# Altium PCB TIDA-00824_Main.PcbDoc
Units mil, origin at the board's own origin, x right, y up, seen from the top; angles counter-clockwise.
Board outline 1575 x 1140 mil, 4 copper layers (Top Layer, GND, PWR, Bottom Layer), stack 60.8 mil thick; 37 components, 28 nets, 124 pads, 44 vias.
Unrouted connection lines stored in the file: 2.
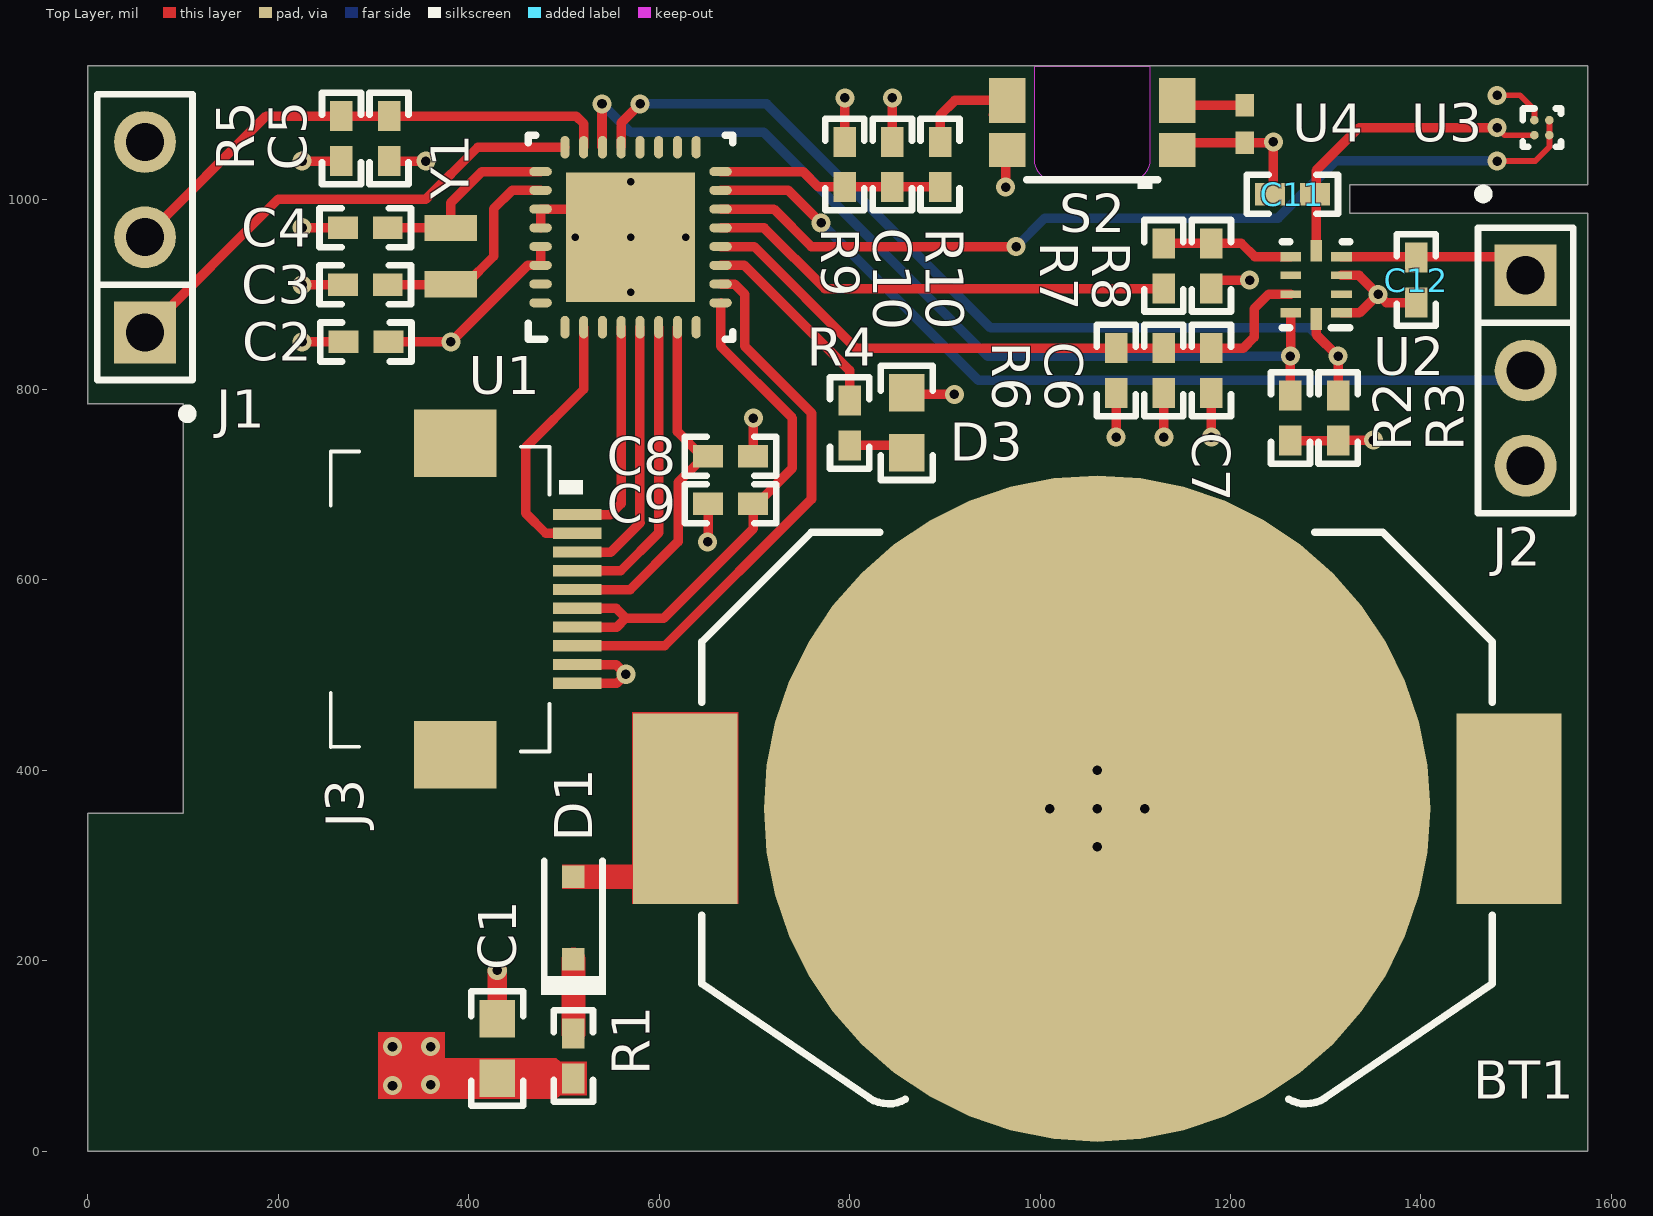
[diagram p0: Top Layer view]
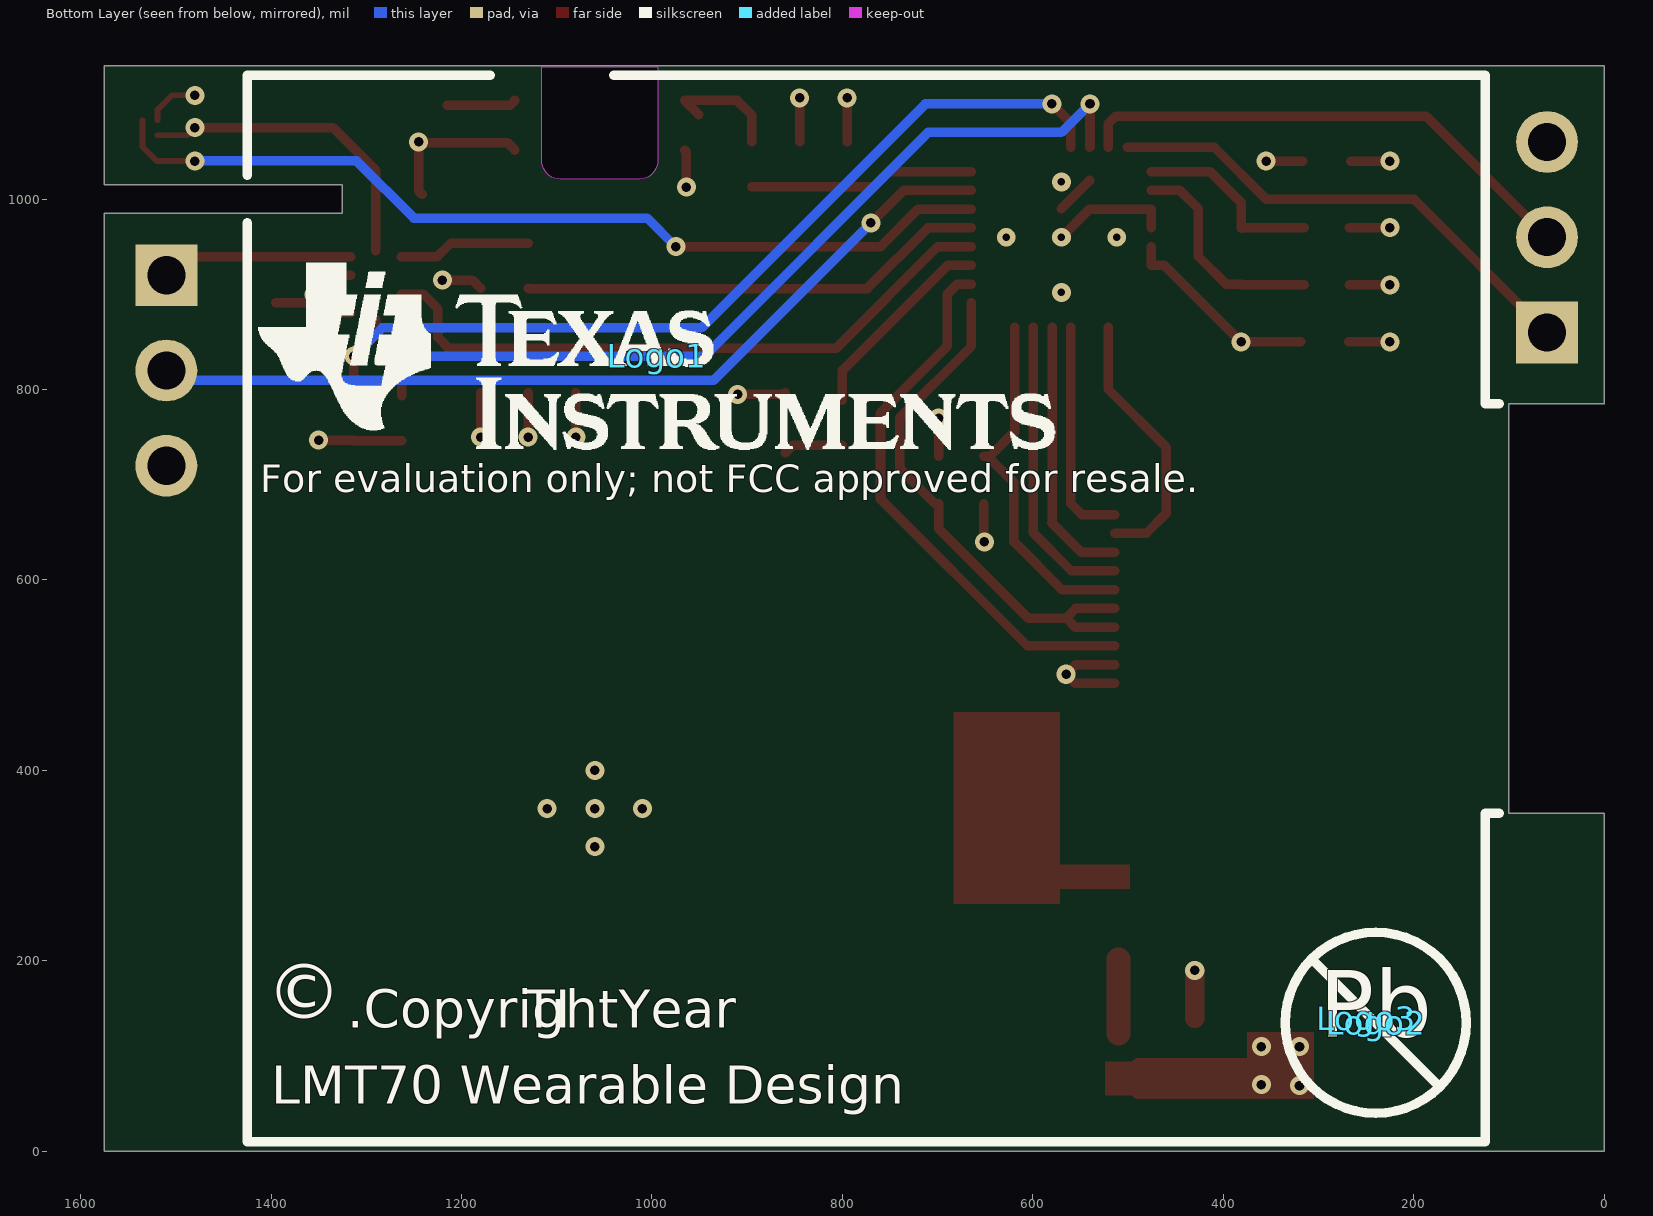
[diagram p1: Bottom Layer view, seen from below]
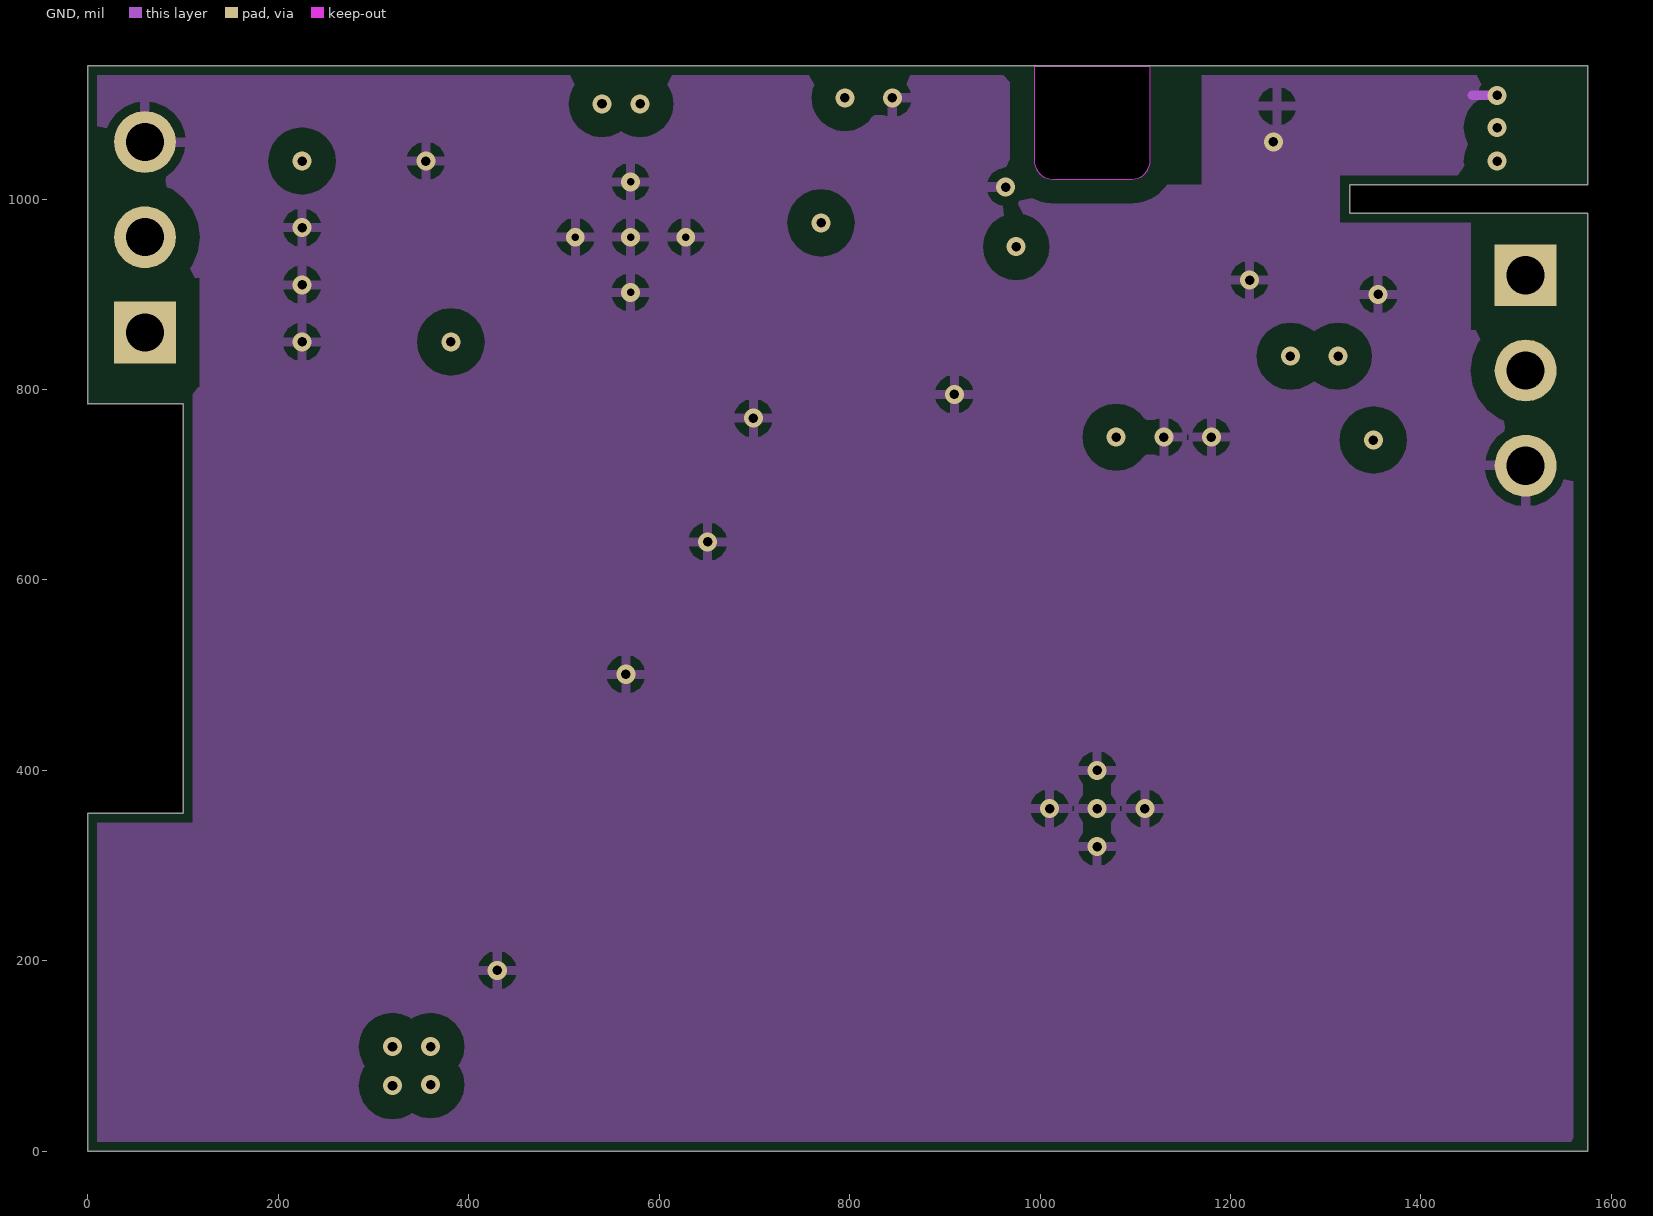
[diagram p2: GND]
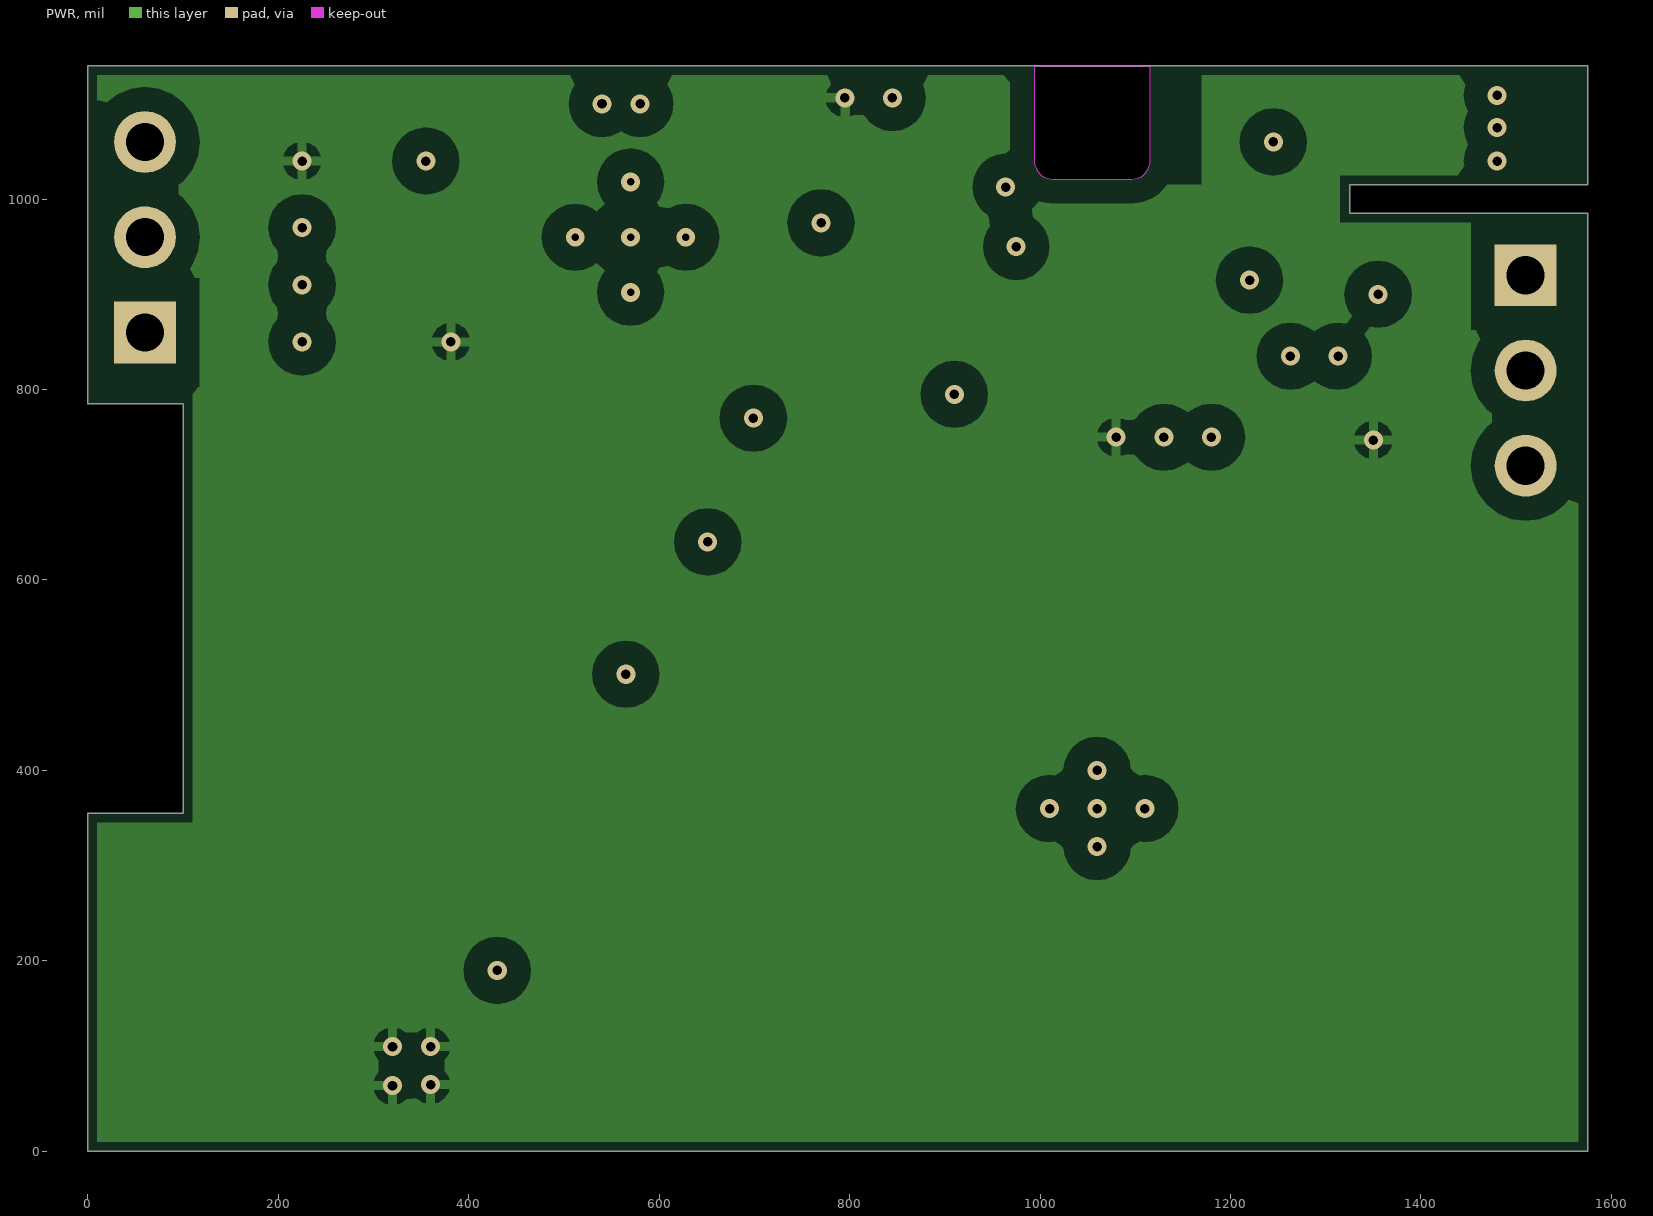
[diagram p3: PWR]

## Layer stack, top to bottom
Top Solder: solder mask 0.4, Solder Resist, Dk 3.5
Top Layer: signal copper 1.4
Dielectric1: core 12.6, FR-4, Dk 4.8
GND: signal copper 1.4
Dielectric2: prepreg 30, FR-4, Dk 4.8
PWR: signal copper 1.4
Dielectric3: core 12.6, FR-4, Dk 4.8
Bottom Layer: signal copper 1.4
Bottom Solder: solder mask 0.4, Solder Resist, Dk 3.5

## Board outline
0,0 0,355 100,355 100,785 0,785 0,1140 1575,1140 1575,1015 1325,1015 1325,985 1575,985 1575,0

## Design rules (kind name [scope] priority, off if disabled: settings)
AcuteAngle [All] p1: minimum=4.50000000000000E+0001 checktracksonly=FALSE
AssemblyTestPointUsage [All] p1: valid=2
Clearance Clearance_BoardEdge_MountingHoles [OnCopper and InComponentClass('Mounting Holes') vs IsKeepOut] p1: gap=40
Clearance Clearance_BoardEdge_Poly [OnCopper and InPoly vs IsKeepOut] p2: gap=25
Clearance Clearance_BoardEdge [OnCopper and Not InComponentClass('Logo') and not InComponentClass('FiducialMark') and not InRegion(1000,500,4000,800) and Not IsKeepout vs IsKeepOut] p3: gap=75
Clearance Clearance_Poly [InPolygon] p4: gap=25
Clearance [All] p5: gap=7.87
ComponentClearance ComponentClearance_Shunt [InComponentClass('Header') vs InComponentClass('Shunt')] p1: gap=0 collisioncheckmode=3 verticalgap=0 showdistances=FALSE
ComponentClearance ComponentClearance_MountingHoles_FiducialMarks [InComponentClass('Mounting Holes') vs InComponentClass('FiducialMark')] p2: gap=50 collisioncheckmode=3 verticalgap=10 showdistances=FALSE
ComponentClearance ComponentClearance_Logo [InComponentClass('Logo')] p3: gap=50 collisioncheckmode=3 verticalgap=10 showdistances=FALSE
ComponentClearance ComponentClearance_ScrewToNut [(HasFootprint('NY PMS 440 0025 PH')) vs (HasFootprint('Keystone_1902C'))] p4: gap=5 collisioncheckmode=3 verticalgap=10 showdistances=FALSE
ComponentClearance ComponentClearance_MountingHoles [InComponentClass('Mounting Holes')] p5: gap=250 collisioncheckmode=3 verticalgap=100000 showdistances=FALSE
ComponentClearance ComponentClearance_SmallPassives [HasFootprint('0201*') or HasFootprint('0402*') or HasFootprint('0508') or HasFootprint('0603*') or HasFootprint('0612') or HasFootprint('0805*') or HasFootprint('0815*') or HasFootprint('0830*') or HasFootprint('1206*') or HasFootprint('1210*') or HasFootprint('1808*') or HasFootprint('1812*') or HasFootprint('1825*') or HasFootprint('2010*') or HasFootprint('2220*') or HasFootprint('2225*') or HasFootprint('2512*') or HasFootprint('2728*') or HasFootprint('3518*') vs HasFootprint('0201*') or HasFootprint('0402*') or HasFootprint('0508') or HasFootprint('0603*') or HasFootprint('0612') or HasFootprint('0805*') or HasFootprint('0815*') or HasFootprint('0830*') or HasFootprint('1206*') or HasFootprint('1210*') or HasFootprint('1808*') or HasFootprint('1812*') or HasFootprint('1825*') or HasFootprint('2010*') or HasFootprint('2220*') or HasFootprint('2225*') or HasFootprint('2512*') or HasFootprint('2728*') or HasFootprint('3518*')] p6: gap=20 collisioncheckmode=3 verticalgap=10 showdistances=FALSE
ComponentClearance ComponentClearance_THtoSMT [IsThruComponent vs IsSMTComponent] p7: gap=50 collisioncheckmode=3 verticalgap=30 showdistances=FALSE
ComponentClearance ComponentClearance_THtoTH [IsThruComponent vs IsThruComponent] p8: gap=118.11 collisioncheckmode=3 verticalgap=30 showdistances=FALSE
ComponentClearance [All] p9: gap=40 collisioncheckmode=3 verticalgap=10 showdistances=FALSE
DiffPairsRouting [All] p1: maxlimit=100 minlimit=10 mostfreqgap=10 toplayer_minwidth=15 toplayer_maxwidth=15 toplayer_prefwidth=15 midlayer1_minwidth=15 midlayer1_maxwidth=15 midlayer1_prefwidth=15 midlayer2_minwidth=15 midlayer2_maxwidth=15 midlayer2_prefwidth=15 bottomlayer_minwidth=15 bottomlayer_maxwidth=15 bottomlayer_prefwidth=15 maxuncoupledlength=1000
FabricationTestPointUsage TestPointUsage [All] p1: valid=2 allowmultiple=FALSE
FabricationTestpoint Testpoint [All] p1: side=3 testpointundercomponent=TRUE minsize=40 maxsize=100 preferedsize=60 minholesize=0 maxholesize=40 preferedholesize=32 testpointgrid=1 allowsidetop=TRUE allowsidebottom=TRUE usegrid=TRUE gridtolerance=0.01
FanoutControl Fanout_LCC [IsLCC] p1: bgadir=Out bgaviamode=Centered fanoutstyle=Auto fanoutdirection=Alternating viagrid=1 // Fanout_LCC (Default Rule)
FanoutControl Fanout_BGA [IsBGA] p2: bgadir=Out bgaviamode=Centered fanoutstyle=Auto fanoutdirection=Alternating viagrid=1 // Fanout_BGA (Default Rule)
FanoutControl Fanout_Default [All] p4: bgadir=Out bgaviamode=Centered fanoutstyle=Auto fanoutdirection=Alternating viagrid=1 // Fanout_Default (Default Rule)
FanoutControl Fanout_Small [(CompPinCount < 5)] p5: bgadir=Out bgaviamode=Centered fanoutstyle=Auto fanoutdirection=OutThenIn viagrid=1 // Fanout_Small (Default Rule)
HoleSize [All] p1: absolutevalues=TRUE maxlimit=251 minlimit=7.87 maxpercent=80.000 minpercent=20.000
MinimumAnnularRing MinimumAnnularRing_ThermalPadVias [IsVia and InAnyComponent] p1: minimumring=5.91
MinimumAnnularRing [All] p2: minimumring=5
MinimumSolderMaskSliver MinimumSolderMaskSliver_Logo [InComponentClass('Logo') vs InComponentClass('Logo')] p1: minsoldermaskwidth=0.7
MinimumSolderMaskSliver [All] p2: minsoldermaskwidth=3.94
PlaneConnect [All] p1: planeconnectstyle=Relief reliefexpansion=10 reliefentries=4 reliefconductorwidth=10 reliefairgap=10
PolygonConnect [All] p1: connectstyle=Relief reliefconductorwidth=10 reliefentries=4 polygonreliefangle="90 Angle" airgapwidth=10
RoutingVias ThermalPadVias [IsVia and InAnyComponent] p1: holewidth=7.87 width=19.68 viastyle="Through Hole" minholewidth=7.87 minwidth=19.68 maxholewidth=12.99 maxwidth=23.62
RoutingVias [All] p2: holewidth=16 width=34 viastyle="Through Hole" minholewidth=7.87 minwidth=26 maxholewidth=40 maxwidth=65
SMDToCorner [All] p1 off: distance=30000
SilkToSilkClearance SilkToSilkClearance_Pb-FreeLogo [(HasFootprint('Pb-Free_Overlay_Medium') OR HasFootprint('Pb-Free_Overlay_Small')) vs (HasFootprint('Pb-Free_Overlay_Medium') OR HasFootprint('Pb-Free_Overlay_Small'))] p1: silktosilkclearance=0
SilkToSilkClearance [All] p2: silktosilkclearance=5
SilkToSolderMaskClearance SilkscreenOverComponentPads [IsPad] p1: minsilkscreentomaskgap=5 clearancetoexposedcopper=TRUE
SolderMaskExpansion [All] p1: expansion=1.97
UnpouredPolygon [All] p1: allowunpoured=FALSE
Width [All] p1: maxlimit=100 minlimit=6 preferedwidth=10 checkconnectedcopper=TRUE
15 further rules are at their usual default settings.

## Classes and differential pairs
component class Header: J1 J2
component class Logo: Logo1

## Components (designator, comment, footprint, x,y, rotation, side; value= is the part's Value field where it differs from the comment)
BT1 "BK-912" MPD_BK-912 1060,360 r0 top
C1 "C1608X5R1A106M" 0603 430,108 r90 top
C2 "GRM155R71C104JA88D" 0402 292,850 r180 top
C3 "GRM1555C1E120JA01D" 0402 291.38,910 r0 top
C4 "GRM1555C1E120JA01D" 0402 291.38,970 r0 top
C5 "C1005X7R1H222K" 0402 316.38,1063.62 r270 top
C6 "GRM155R71C104JA88D" 0402 1130,820 r270 top
C7 "GRM1535C1H101JDD5D" 0402 1180,820 r270 top
C8 "GRM155R71C104JA88D" 0402 675,730 r0 top
C9 "GRM155R6YA105KE11D" 0402 675,680 r180 top
C10 "GRM155R6YA105KE11D" 0402 845,1036.38 r90 top
C11 "GRM155R61E102KA01D" 0402 1265,1005 r180 top
C12 "GRM155R61E102KA01D" 0402 1395,915 r270 top
D1 "1SS315TPH3F" sod-323 510,245 r90 top
D3 "SML-LX0603SRW-TR" 0603 860,765 r90 top
J1 "TSW-103-07-G-S" TSW-103-07-G-S 60,960 r90 top
J2 "TSW-103-07-G-S" TSW-103-07-G-S 1510,820 r270 top
J3 "FH12-10S-0.5SH[55]" Hirose_FH12-10S-0_5SH[55] 450,580 r270 top
Logo1 "Texas Instruments" TI_Stacked_Overlay_Small 995,835 r180 bottom
Logo2 "Pb-Free Symbol" Pb-Free_Overlay_Medium 240,135 r180 bottom
Logo3 "FCC disclaimer" FCC_disclaimer 250,140 r180 bottom
R1 "CRCW040212R1FKED" 0402 510,100 r270 top
R2 "CRCW040210K0JNED" 0402 1263,770 r270 top
R3 "CRCW040210K0JNED" 0402 1313,770 r270 top
R4 "ERJ-2GEJ102X" 0402 800,765 r270 top
R5 "CRCW040233K0JNED" 0402 266.38,1063.62 r90 top
R6 "CRCW04020000Z0ED" 0402 1080,820 r270 top
R7 "CRCW0402100KFKED" 0402 1130,930 r270 top
R8 "CRCW0402100KFKED" 0402 1180,930 r90 top
R9 "CRCW0402100KFKED" 0402 795,1036.38 r270 top
R10 "CRCW0402100KFKED" 0402 895,1036.38 r270 top
S2 "EVP-ANDA1A" SW_EVPANDA 1054.88,1139.05 r180 top
U1 "MSP430G2553IRHB32R" RHB0032E 570,960 r90 top
U2 "ADS1115IRUGR" RUG0010A 1290,910 r180 top
U3 "LMT70YFQR" YFQ0004ACAC 1527.05,1075.08 r0 top
U4 "TPD1E10B06DPYR" DPY0002A 1214.88,1079.05 r270 top
Y1 "FC-12M 32.7680KA-A3" Epson_FC-12M 381.38,940 r270 top

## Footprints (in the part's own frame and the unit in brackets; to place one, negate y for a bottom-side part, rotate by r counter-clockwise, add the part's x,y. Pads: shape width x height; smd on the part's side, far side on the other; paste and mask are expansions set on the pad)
0402 [mm] "0402 from SM-752 data"
  rect 0.8x0.6 smd: 1(-0.6,0) 2(0.6,0)
  silkscreen extent -1.22,-0.52 1.22,0.52, body extent -0.55,-0.3 0.55,0.3, height 0.6
0603 [mm] "0603 from SM-752 data"
  rect 1x0.95 smd: 1(-0.8,0) 2(0.8,0)
  silkscreen extent -1.52,-0.69 1.52,0.69, body extent -0.87,-0.47 0.87,0.47, height 0.85
DPY0002A [mm] "R-PX2SON-N2"
  rect 0.6x0.5 smd: 1(-0.5,0) 2(0.5,0)
  body extent -0.55,-0.35 0.55,0.35, height 0.4
Epson_FC-12M [mm] "Epson"
  rect 0.7x1.4 smd: 1(-0.75,0) 2(0.75,0)
  body extent -1.05,-0.63 1.05,0.63, height 0.6
FCC_disclaimer [mil]
Hirose_FH12-10S-0_5SH[55] [mm] "Hirose, footprint recommended"
  rect 0.3x1.3 smd: 1(-2.254,1.626) 2(-1.754,1.626) 3(-1.254,1.626) 4(-0.754,1.626) 5(-0.253,1.626) 6(0.246,1.626) 7(0.746,1.626) 8(1.246,1.626) 9(1.746,1.626) 10(2.247,1.626)
  rect 1.8x2.2 smd: M1(-4.153,-1.622) M2(4.153,-1.626)
  silkscreen extent -4.06,-4.95 4.07,1.78, body extent -4.55,-4.88 4.56,0.84, height 2
MPD_BK-912 [mm] "Battery Holder for CR2032, SMT"
  rect 2.79x5.08 smd: 1(-10.985,0) 2(10.985,0)
  round 17.78 smd: 3(0,0)
  silkscreen extent -10.54,-7.88 10.54,7.37, body extent -11.43,-7.88 11.43,7.37, height 4.33
Pb-Free_Overlay_Medium [mil]
  silkscreen extent -95,-95 95,95
RHB0032E [mm] "QFN, 32-Leads, Body 5x5mm, Pitch 0.5mm, Thermal Pad 3.45x3.45mm, TI Recommended"
  oval 0.6x0.24 smd: 1(-2.4,1.75) 2(-2.4,1.25) 3(-2.4,0.75) 4(-2.4,0.25) 5(-2.4,-0.25) 6(-2.4,-0.75) 7(-2.4,-1.25) 8(-2.4,-1.75) 17(2.4,-1.75) 18(2.4,-1.25) 19(2.4,-0.75) 20(2.4,-0.25) 21(2.4,0.25) 22(2.4,0.75) 23(2.4,1.25) 24(2.4,1.75)
  oval 0.24x0.6 smd: 9(-1.75,-2.4) 10(-1.25,-2.4) 11(-0.75,-2.4) 12(-0.25,-2.4) 13(0.25,-2.4) 14(0.75,-2.4) 15(1.25,-2.4) 16(1.75,-2.4) 25(1.75,2.4) 26(1.25,2.4) 27(0.75,2.4) 28(0.25,2.4) 29(-0.25,2.4) 30(-0.75,2.4) 31(-1.25,2.4) 32(-1.75,2.4)
  rect 3.45x3.45 smd paste-1.725: 33(0,0)
  silkscreen extent -2.72,-2.73 2.72,2.73, body extent -2.57,-2.57 2.58,2.58, height 1.01
RUG0010A [mm] "QFN, 10-Leads, Body 2x1.5mm. Pitch 0.5mm, TI Recommended"
  rect 0.55x0.25 smd: 1(-0.675,0.75) 4(-0.675,-0.75) 6(0.675,-0.75) 9(0.675,0.75)
  rect 0.55x0.2 smd: 2(-0.675,0.25) 3(-0.675,-0.25) 7(0.675,-0.25) 8(0.675,0.25)
  rect 0.3x0.575 smd: 5(0,-0.913) 10(0,0.913)
  silkscreen extent -0.9,-1.15 0.9,1.15, body extent -0.77,-1.02 0.77,1.02, height 0.41
sod-323 [mm] "NXP recommended land pattern"
  rect 0.6x0.6 smd paste-0.05: 1(-1.1,0) 2(1.1,0)
  silkscreen extent -2.06,-0.86 1.53,0.86, body extent -1.3,-0.67 1.3,0.68, height 1.1
SW_EVPANDA [mm] "SMT, 4-Leads, Body 3.5x2.9mm, Pitch 1.325mm"
  rect 0.975x0.9 smd mask-5: 1(-2.262,2.225) 2(2.262,2.225)
  rect 0.975x1.2 smd mask-5: 3(-2.262,0.9) 4(2.262,0.9)
  Keep-Out Layer board cut-out: -1.55,0 1.55,0 1.55,2.5 1.512,2.691 1.404,2.854 1.241,2.962 1.05,3 1.05,3 -1.05,3 -1.241,2.962 -1.404,2.854 -1.512,2.691 -1.55,2.5 -1.55,2.5
  silkscreen extent -1.75,3.01 1.75,3.26, body extent -2.6,-0.49 2.6,3.22, height 0.85
TI_Stacked_Overlay_Small [mil]
  silkscreen extent -418,-98 418,98
TSW-103-07-G-S [mm] "Samtec 100mil, 1x3, 230 mil above insulator"
  rect 1.65x1.65 hole 1.016: 1(-2.54,0)
  round 1.65 hole 1.016: 2(0,0) 3(2.54,0)
  silkscreen extent -4.83,-1.27 3.81,1.27, body extent -3.81,-1.27 3.81,1.27, height 8.38
YFQ0004ACAC [mm] "WCSP, 4-Leads, Body 0.84x0.84mm, Pitch 0.4mm"
  round 0.23 smd paste-0.13 mask+0.038: A1(-0.2,0.2) A2(0.2,0.2) B1(-0.2,-0.2) B2(0.2,-0.2)
  silkscreen extent -0.51,-0.51 0.51,0.51, body extent -0.42,-0.42 0.42,0.42, height 0.58

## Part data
BT1: "Battery Holder for CR2032, SMT"
C1: "CAP, CERM, 10 µF, 10 V, +/- 20%, X5R, 0603"
C2 C6 C8: library part 0402YC132KAT2A, "CAP CER 0.1UF 16V 5% X7R 0402"
C3 C4: "CAP, CERM, 12 pF, 25 V, +/- 5%, C0G/NP0, 0402"
C5: "CAP, CERM, 2200 pF, 50 V, +/- 10%, X7R, 0402"
C7: "CAP, CERM, 100 pF, 50 V, +/- 5%, C0G/NP0, 0402"
C9 C10: "CAP, CERM, 1 µF, 35 V, +/- 10%, X5R, 0402"
C11 C12: "CAP, CERM, 1000 pF, 25 V, +/- 10%, X5R, 0402"
D1: "Diode, Schottky, 5 V, 0.03 A, SOD-323"
D3: library part LED, "LED 660NM SUPER RED DIFF 0603SMD"
J1 J2: "Header, 100mil, 3x1, Gold, TH"
J3: "Connector, FPC 10 Pos. 9.1x2.0x5.6 mm"
Logo1: library part TI_Logo, "Texas Instrument Corporate Signature"
Logo2: library part Pb-Free
Logo3: library part FCC_disclaimer, "FCC_disclaimer"
R1: "RES, 12.1, 1%, 0.063 W, 0402"
R2 R3: "RES, 10 k, 5%, 0.063 W, 0402"
R4: library part CRCW040233R0JNED, "RES 1K OHM 1/10W 5% 0402 SMD"
R5: "RES, 33k ohm, 5%, 0.063W, 0402"
R6: "RES, 0, 5%, 0.063 W, 0402"
R7 R8 R9 R10: "RES, 100 k, 1%, 0.063 W, 0402"
S2: "Switch, Slide, SPST-NO,  Off-Mom, 0.05 A,  12V, SMD"
U1: "16 MHz Mixed Signal Microcontroller with 16 KB Flash, 512 B SRAM and 24 GPIOs, -40 to 85 degC, 32-pin QFN (RHB), Green (RoHS & no Sb/Br)"
U2: "Ultra-Small, Low-Power, 16-Bit Analog-to-Digital Converter with Internal Reference, RUG0010A"
U3: "±0.1°C Precision Analog Temperature Sensor, RTD and Precision NTC Thermistor IC, YFQ0004ACAC"
U4: "ESD in 0402 Package with 10 pF Capacitance and 6 V Breakdown, 1 Channel, -40 to +125 degC, 2-pin X2SON (DPY), Green (RoHS & no Sb/Br)"
Y1: "Crystal, 32.768kHz, 12.5pF, SMD"

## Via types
v1: diameter 20, hole 10, Top Layer to Bottom Layer, tented both sides, 33 vias
v2: diameter 20, hole 10, Top Layer to Bottom Layer, 6 vias
v3: diameter 19.68, hole 7.87, Top Layer to Bottom Layer, 5 vias

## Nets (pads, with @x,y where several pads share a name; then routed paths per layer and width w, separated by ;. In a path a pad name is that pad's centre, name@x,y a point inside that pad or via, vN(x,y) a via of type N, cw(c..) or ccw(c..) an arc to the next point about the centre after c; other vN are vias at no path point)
"ADC SCL": R3.1 U1.21 U2.10 | length 986.6
  Top Layer w10: U1.21 560,1054.65 560,1080 v1(580,1100) ; U2.10 1290,858 v1(1313,835) R3.1
  Bottom Layer w10: v1(580,1100) 712.8,1100 948.07,864.72 1283.28,864.72 v1(1313,835)
"ADC SDA": R2.1 U1.22 U2.9 | length 964.9
  Top Layer w10: v1(540,1100) 540,1054.96 U1.22 ; R2.1 v1(1263,835) ; v1@1263.43,835.43 U2.9
  Bottom Layer w10: v1(540,1100) 570,1070 710,1070 945,835 v1(1263,835)
"ADC VDD": C6.1 C7.1 R6.1 U1.12 U2.8 | length 684.1
  Top Layer w10: U1.12 699.84,950.16 806.38,843.62 C6.1 C7.1 1213.62,843.62 1225,855 1225,885 1240.16,900.16 U2.8
BATTERY: R7.2 U1.13 | length 492.1
  Top Layer w10: U1.13 710.16,969.84 774,906 1129.62,906 R7.2
GND: BT1.3 C1.2 C2.2 C3.1 C4.1 C5.2 C6.2 C7.2 C8.2 C9.2 C10.2 C11.2 C12.2 D3.2 J1.3 J2.3 J3.9 J3.10 R8.1 S2.1 S2.2 U1.27 U1.28 U1.33 U2.1 U2.3 U3.A1 U4.2 | length 1229.7
  Top Layer w6: v1(1480,1109) 1504,1109 1519.17,1093.83 U3.A1
  Top Layer w10: v1(225,850) C2.2 ; v1(225,910) C3.1 ; v1(225,970) C4.1 ; C5.2 v1(355,1040) ; U1.28 U1.27 540.47,989.53 v3(570,960) ; J3.10 555.56,491.56 v1(565,501) 554.76,511.24 J3.9 ; U1.33@540.47,1019.53 U1.33@570,990 ; v1(651,640) 651.38,640.38 C9.2 ; C8.2 699,730.38 v1(699,770) ; C10.2 v1(845,1106.38) ; D3.2 861.5,795 v2(910,795) ; v1(963.88,1012.68) 963.88,1049.53 S2.2 ; v1(1130,750) C6.2 ; S2.1 1151.87,1059.37 U4.2 1244.37,1059.37 v1(1245,1060) 1245,1008.62 C11.2 ; v1(1180,750) C7.2 ; R8.1 1188.62,915 v1(1220,915) ; U2.1 1335.47,880.47 v1(1355,900) ; U2.3 1335.16,919.84 v1(1355,900) ; C12.2 1363.62,891.38 v1(1355,900)
  Top Layer w20: C1.2 v1(430,190)
  GND w10: 1454,1109 v1(1480,1109)
  other v2: 1060,320 1010,360 1060,360 1110,360 1060,400
  other v3: 570,901.93 511.93,960 628.07,960 570,1018.07
"LCD CS": J3.3 U1.5 | length 284.3
  Top Layer w10: J3.3 549.35,629.35 580,660 579.84,660.16 U1.5
"LCD DISP": C8.1 J3.5 U1.7 | length 378
  Top Layer w10: J3.5 569.7,589.98 620,640.28 620,702.5 647.5,730 C8.1 ; U1.7 619.21,755.79 C8.1@645,730
"LCD EXT MODE": J3.8 U1.10 | length 583.8
  Top Layer w10: J3.8 605.93,530.93 760,685 760,775.28 690,845.28 690,900 679.21,910.79 U1.10
"LCD EXTCOMIN": J3.4 U1.6 | length 318
  Top Layer w10: J3.4 559.67,609.67 599.53,649.53 U1.6
"LCD ON": C10.1 R9.2 R10.2 U1.16 | length 287.3
  Top Layer w10: U1.16 751.1,1028.9 767.13,1012.87 C10.1@845,1012.87 ; R9.2@795,1012.87 R9.2 C10.1 R10.2
"LCD SCLK": J3.1 U1.4 | length 236.2
  Top Layer w10: J3.1 548.72,668.72 560.16,680.16 U1.4
"LCD SDATA": J3.2 U1.2 | length 283.4
  Top Layer w10: J3.2 480.96,649.04 460,670 460,739.52 520.79,800.31 U1.2
"LCD VDD": C9.1 J3.6 J3.7 U1.9 | length 570.7
  Top Layer w10: J3.7 555.61,550.61 565,560 ; J3.6 554.7,570.3 565,560 ; U1.9 664.49,845.51 740,770 740,717.5 702.5,680 C9.1 698.62,653.62 605,560 565,560
"LMT70 AMBI TAO": C11.1 U2.5 U3.B1 | length 335.1
  Top Layer w6: v1@1480.06,1074.94 1487.8,1067.2 U3.B1
  Top Layer w10: U2.5 1290,1030 1335.12,1075.12 v1@1480.06,1074.94
  other v1: 1480,1075
"LMT70 AMBI TON": U1.14 U3.A2 U3.B2 | length 958.2
  Top Layer w6: v1(1480,1040) 1520,1040 1534.92,1054.92 U3.B2 U3.A2
  Top Layer w10: U1.14 720.47,989.53 760,950 v1(975,950)
  Bottom Layer w10: v1(975,950) 1005,980 1250,980 1310.16,1040.16 v1@1479.84,1040.16
"LMT70 SKIN TAO": C12.1 J2.1 U2.4 | length 201.5
  Top Layer w10: U2.4 1490.47,939.53 J2.1
"LMT70 SKIN TON": J2.2 U1.15 | length 932.2
  Top Layer w10: U1.15 735.79,1009.21 v1(770,975)
  Bottom Layer w10: v1(770,975) 935,810 1500,810 J2.2
NetBT1_1: BT1.1 BT1.2 D1.2
NetC3_2: C3.2 U1.26 Y1.2 | length 230.9
  Top Layer w10: C3.2 380.91,910 Y1.2 396.85,910.47 426.38,940 426.38,990 445.59,1009.21 U1.26
NetC4_2: C4.2 U1.25 Y1.1 | length 201
  Top Layer w10: C4.2 380.91,970 Y1.1 381.38,996.38 413.9,1028.9 U1.25
NetD1_1: D1.1 R1.1 | length 78.1
  Top Layer w25: R1.1 D1.1
NetD3_1: D3.1 R4.2 | length 63.3
  Top Layer w10: R4.2 852.13,741.38 D3.1
NetR4_1: R4.1 U1.11 | length 212.6
  Top Layer w10: U1.11 689.53,930.47 800,820 R4.1
NetR7_1: R7.1 R8.2 U2.6 | length 139.3
  Top Layer w10: R7.1 R8.2 1211.38,953.62 1225.47,939.53 U2.6
NetR10_1: R10.1 S2.3 S2.4 U4.1 | length 199.3
  Top Layer w10: R10.1 895,1088 910.62,1103.62 S2.4 S2.4@950.92,1088.74 ; S2.3 1148.84,1098.74 U4.1
SBWTCK: J1.1 U1.24 | length 521.7
  Top Layer w10: J1.1 200,1000 355,1000 409.49,1054.49 U1.24
SBWTDIO: C5.1 J1.2 R5.2 U1.23 | length 571.5
  Top Layer w10: J1.2 187.24,1087.24 346.38,1087.24 ; C5.1 512.76,1087.24 520.79,1079.21 U1.23
VDD: C1.1 C2.1 R1.2 R2.2 R3.2 R5.1 R6.2 R9.1 U1.29 U1.30 | length 431.5
  Top Layer w10: v1(225,1040) R5.1 ; C2.1@318.62,850 v1(381.38,850) 461.85,930.47 U1.30 U1.29 ; R1.2@509.87,76.5 R1.2 ; R9.1 v1(795,1106.38) ; v1(1080,750) R6.2 ; R2.2 R3.2 1313.62,747 v1(1350,747)
  other v1: 320,69 360,70 320,110 360,110
pads on no net: J3.M1 J3.M2 U1.1 U1.3 U1.8 U1.17 U1.18 U1.19 U1.20 U1.31 U1.32 U2.2 U2.7

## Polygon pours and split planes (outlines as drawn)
GND on GND "GND-No Net" (solid, remove dead copper, pour order 4): 10,1130 10,795 110,795 110,345 10,345 10,10 1565,10 1560,15 1560,975 1315,975 1315,1025 1565,1025 1565,1130 1170,1130 1170,1015 1040,1015 1040,1130 10,1130
VDD on PWR "PWR-No Net" (solid, remove dead copper, pour order 6): 10,1130 10,795 110,795 110,345 10,345 10,10 1565,10 1565,975 1315,975 1315,1025 1565,1025 1565,1130 1170,1130 1170,1015 1045,1015 1040,1020 1040,1130 10,1130

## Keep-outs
Keep-Out Layer:
  text ".Layer_Name" at 577,-858.49 h60

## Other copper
Top Layer:
  region net NetBT1_1: 498,276 498,301 572,301 572,461 683,461 683,260 572,260 572,276
  region net VDD: 524,59 524,94 496,94 492,98 375,98 375,125 305,125 305,55 492,55 496,59
  text ".Layer_Name" at 577,-858.49 h60
Bottom Layer:
  text ".Layer_Name" at 577,-858.49 h60

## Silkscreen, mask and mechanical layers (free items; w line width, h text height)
Top Overlay:
  text ".Layer_Name" at 577,-858.49 h60
Bottom Overlay:
  lines w10: 110,355 125,355 125,10 1425,10 1425,975 ; 110,785 125,785 125,1130 1040,1130 ; 1170,1130 1425,1130 1425,1025
  text "TI" at 1135,130 h40
  text ".CopyrightYear" at 1320,130 h40
  text "©" at 1405,120 h100
  text "LMT70 Wearable Design" at 1400,50 h40
  text ".Layer_Name" at 577,-858.49 h60
Top Paste:
  text ".Layer_Name" at 577,-858.49 h60
Bottom Paste:
  text ".Layer_Name" at 577,-858.49 h60
Top Solder:
  text ".Layer_Name" at 577,-858.49 h60
  text ".Layer_Name" at 577,-858.49 h60
Bottom Solder:
  text ".Layer_Name" at 577,-858.49 h60
Drill Guide:
  text ".Layer_Name" at 577,-858.49 h60
M1 Board Outline:
  lines w10: 0,785 0,1140 ; 0,785 0,785 ; 0,785 100,785 100,355 0,355 0,0 1575,0 1575,985 1325,985 1325,1015 1575,1015 1575,1140 ; 0,785 0,785 ; 0,785 0,785 ; 0,1140 0,1140 ; 0,1140 0,1140 ; 0,1140 1575,1140 ; 1575,1140 1575,1140
  text ".Layer_Name" at 577,-858.49 h60
M2 Board Dimensions:
  rectangle: 125,-410.5 500,-285.5
  rectangle: 0,-285.5 125,-160.5
  lines w7: 0,-285.5 1000,-285.5 ; 125,-410.5 125,-160.5 ; 250,-410.5 250,-160.5 ; 500,-410.5 500,-160.5 ; 750,-410.5 750,-160.5 ; 0,-410.5 0,-160.5 1000,-160.5 1000,-410.5 0,-410.5
  text ".Layer_Name" at 577,-858.49 h60
M3 3D STEP Top:
  text ".Layer_Name" at 577,-858.49 h60
M4 3D STEP Bottom:
  text ".Layer_Name" at 577,-858.49 h60
M5 Assembly Top:
  lines w10: -292,-930.17 6308,-930.17 ; -292,-726.83 6310,-726.83 ; -292,-523.5 -292,-1133.5 3713,-1133.5 6310,-1133.5 6310,-523.5 -291.5,-523.5 -291.5,-1133.5 1284,-1133.5 ; 2173,-1133.5 2173,-523.5 ; 3440,-726.83 3440,-523.5 ; 4280,-726.83 4280,-523.5 ; 4902,-1140 4902,-937.17
  text "COMPONENTS MARKED 'DNP' SHOULD NOT BE POPULATED." at 1153.5,-318.5 h60
  text "ASSEMBLY VARIANT:" at 1153,-434 h60
  text ".VariantName" at 2189,-434 h60
  text "PCB VIEWED FROM TOP SIDE" at -228.5,-655.67 h60
  text "BOARD #:" at 2248,-655.67 h60
  text ".PRJ_Number" at 2793.5,-655.67 h60
  text "REV:" at 3638,-655.67 h60
  text ".PCB_Rev" at 3929.5,-655.67 h60
  text "SVN REV:" at 4476,-655.67 h60
  text ".VersionControl_RevNumber" at 4982,-655.67 h60
  text "IGNORE ->" at -228.5,-858.49 h60
  text "PLOT NAME =" at -228.5,-1064.34 h60
  text ".plot_File_Name" at 577,-1064.34 h60
  text "GENERATED    :" at 2250,-1064.34 h60
  text ".Print_Date" at 3119.5,-1064.34 h60
  text ".Print_Time" at 3848.5,-1064.34 h60
  text "TEXAS INSTRUMENTS" at 5113,-1064.34 h60
M6 Assembly Bottom:
  lines w10: -292.5,-727.33 6309.5,-727.33 ; -290.5,-930.67 6309.5,-930.67 ; 1115.5,-1140.5 1115.5,-937.67 ; 1737.5,-727.33 1737.5,-524 ; 2577.5,-727.33 2577.5,-524 ; 3844.5,-1134 3844.5,-524 ; 4733.5,-1134 6309,-1134 6309,-524 -292.5,-524 -292.5,-1134 2304.5,-1134 6309.5,-1134 6309.5,-524
  text "COMPONENTS MARKED 'DNP' SHOULD NOT BE POPULATED." at 6102,-318 h60
  text ".VariantName" at 5058,-434 h60
  text "ASSEMBLY VARIANT:" at 6097,-434 h60
  text ".VersionControl_RevNumber" at 1035.5,-656.17 h60
  text "SVN REV:" at 1541.5,-656.17 h60
  text ".PCB_Rev" at 2088,-656.17 h60
  text "REV:" at 2379.5,-656.17 h60
  text ".PRJ_Number" at 3224,-656.17 h60
  text "BOARD #:" at 3769.5,-656.17 h60
  text "PCB VIEWED FROM BOTTOM SIDE" at 6246,-656.17 h60
  text "IGNORE ->" at 2547.85,-858.49 h60
  text "TEXAS INSTRUMENTS" at 904.5,-1064.84 h60
  text ".Print_Time" at 2169,-1064.84 h60
  text ".Print_Date" at 2898,-1064.84 h60
  text "GENERATED    :" at 3767.5,-1064.84 h60
  text ".plot_File_Name" at 5440.5,-1064.84 h60
  text "PLOT NAME =" at 6246,-1064.84 h60
M9 Title Sheet:
  drawing of 57 lines, arcs and shapes, not listed
  text "1" at 739.84,8036.5 h70
  text "2" at 3235.5,8036.5 h70
  text "3" at 5724.84,8036.5 h70
  text "4" at 8231.51,8036.5 h70
  text "5" at 10730.5,8036.5 h70
  text "6" at 13235.5,8036.5 h70
  text "A" at -416.5,6893.5 h70
  text "A" at 14383.5,6893.5 h70
  text "B" at -416.5,4513.5 h70
  text "B" at 14383.5,4513.5 h70
  text "C" at -416.5,2138.5 h70
  text "C" at 14383.5,2138.5 h70
  text "PROJECT TITLE:" at 11343.5,277.5 h45
  text ".PRJ_Title" at 11393.5,144.17 h70
  text "DESIGNED FOR:" at 11343.5,-23.5 h45
  text ".PRJ_Customer" at 11393.5,-163.5 h70
  text "D" at -416.5,-231.5 h70
  text "D" at 14383.5,-231.5 h70
  text "FILE NAME:" at 11343.5,-323.5 h45
  text ".PCB_File_Name_No_Path" at 11393.5,-443.5 h70
  text "Texas Instruments (TI) and/or its licensors do not warrant the accuracy or completeness of this specification" at 6374,-605.34 h45
  text "ENGINEER:" at 11343.5,-613.5 h45
  text "LAYOUT BY:" at 12848.5,-613.5 h45
  text "or any information contained therein. TI and/or its licensors do not warrant that this design will meet" at 6329.01,-718 h45
  text ".PRJ_Engineer" at 11393.5,-768.49 h70
  text ".PCB_Layout" at 12899,-768.49 h70
  text "the specifications, will be suitable for your application or fit for any particular purpose, or will operate in" at 6329.01,-830.67 h45
  text ".Layer_Name" at 577,-858.49 h60
  text "ALTIUM DESIGNER VERSION:" at 12848.5,-923.5 h45
  text "an implementation. TI and/or its licensors do not warrant that the design is production worthy. You should" at 6329.01,-943.33 h45
  text "completely validate and test your design implementation to confirm the system functionality for your application." at 6374,-1056 h45
  text ".print_Scale" at 11393.5,-1056.83 h70
  text ".Application_BuildNumber" at 12899,-1056.83 h70
  text "1" at 739.84,-1263.5 h70
  text "2" at 3235.5,-1263.5 h70
  text "3" at 5724.84,-1263.5 h70
  text "4" at 8231.51,-1263.5 h70
  text "5" at 10730.5,-1263.5 h70
  text "6" at 13235.5,-1263.5 h70
M10 Fab Notes:
  drawing of 185 lines, arcs and shapes, not listed
  text "DESIGN INFORMATION" at 12381.02,5910 h60
  text "MIN. TRACK WIDTH:" at 11736.46,5730 h60
  text "6" at 12832.7,5730 h60
  text "MIL" at 12987.46,5730 h60
  text "MIN. CLEARANCE:" at 11736.46,5598 h60
  text "0.2" at 12772.7,5598 h60
  text "mm" at 12987.46,5598 h60
  text "MIN. VIA PAD SIZE:" at 11736.46,5466 h60
  text "20" at 12802.71,5466 h60
  text "MIL" at 12987.46,5466 h60
  text "0.05mm (2MIL)" at 12431.46,5324.29 h60
  text "MINIMUM ANNULAR RING" at 11407.23,5320 h60
  text "EXTERNAL" at 13139.46,5320 h60
  text "PER" at 11607.23,5202 h60
  text "IPC-D-275 CLASS 2 LEVEL C" at 11827.23,5202 h60
  text "MIL, HOLES" at 13315.46,5089.71 h60
  text "+/-" at 12923,5089 h60
  text "+/-" at 13777,5089 h60
  text "REGISTRATION TOLERANCES:" at 11407.23,5084 h60
  text "METAL" at 12607,5084 h60
  text "5" at 13183.2,5084 h60
  text "3" at 14016.2,5084 h60
  text "MIL" at 14132.46,5084 h60
  text "MATERIAL:" at 11332.46,4874.54 h60
  text "FR-4 High Tg" at 12318.9,4734.21 h60
  text "FR-408" at 11753.46,4725.64 h60
  text "X" at 12165.46,4725.64 h60
  text "OTHER" at 13241.46,4725.64 h60
  text "62 MIL (1.6mm) +/-10%" at 12073.56,4562.92 h60
  text "THICKNESS:" at 11407.23,4558.64 h60
  text "X" at 11945.4,4558.64 h60
  text "OTHER" at 13358.46,4558.64 h60
  text "TOLERANCE:" at 11407.23,4400.64 h60
  text "X" at 12246.53,4400.64 h60
  text "ANSI IPC-6012 TYPE 3 CLASS 2" at 12433.48,4400.64 h60
  text "OTHER +/-" at 12433.46,4244.64 h60
  text "BOW & TWIST:" at 11407.23,4087.64 h60
  text "X" at 12246.53,4087.64 h60
  text "ANSI IPC-6012 TYPE 3 CLASS 2" at 12433.48,4087.64 h60
  text "OTHER +/-" at 12433.46,3929.13 h60
  text "DRILLING:" at 11332.46,3790.64 h60
  text "REFERENCE:" at 11407.23,3673.64 h60
  text "X" at 12055.46,3673.64 h60
  text "AS SHOWN" at 12242.46,3673.64 h60
  text "X" at 12956.46,3673.64 h60
  text "NC_DRILL FILES" at 13093.46,3673.64 h60
  text "PTH MIN COPPER THICKNESS:" at 11407.23,3515.64 h60
  text "X" at 12757.46,3515.64 h60
  text "1MIL" at 12894.46,3515.64 h60
  text "OTHER" at 13391.46,3515.64 h60
  text "BOARD FINISH:" at 11332.46,3356.64 h60
  text "SILKSCREEN:" at 11487.68,3238.64 h60
  text "X" at 12436.46,3238.64 h60
  text "TOP" at 12562.46,3238.64 h60
  text "X" at 12946.46,3238.64 h60
  text "BOTTOM" at 13073.46,3238.64 h60
  text "SILKSCREEN COLOR:" at 11487.68,3071.64 h60
  text "X" at 12435.42,3071.64 h60
  text "WHITE" at 12562.46,3071.64 h60
  text "OTHER" at 13073.46,3071.64 h60
  text "SOLDER RESIST COLOR:" at 11487.68,2901.64 h60
  text "X" at 12055.42,2742.44 h60
  text "GREEN" at 12182.46,2742.44 h60
  text "BLUE" at 12773.46,2742.44 h60
  text "OTHER" at 13311.46,2742.44 h60
  text "IMMERSION GOLD (ENIG)" at 12393.46,2553.92 h60
  text "ENEPIG" at 13731,2550.64 h60
  text "SURFACE FINISH:" at 11332.46,2549.64 h60
  text "X" at 12206.51,2549.64 h60
  text "IMM. TIN/SILVER OR EQUIV" at 11662,2392.64 h60
  text "OTHER" at 13093.46,2392.64 h60
  text "ARRAY/PANEL:" at 11332.46,2213.64 h60
  text "CUT AND TRIM PER MECH LAYER 1" at 12393.46,2209.35 h60
  text "N.C. ROUTE" at 12393.46,2057.64 h60
  text "X" at 13072.46,2057.64 h60
  text "V. SCORE" at 13259.46,2057.64 h60
  text "CERTIFICATION:" at 11332.46,1920.64 h60
  text "MATERIALS AND WORKMANSHIP FOR ALL PCBS" at 12057.46,1920.64 h60
  text "TO MEET OR EXCEED THE REQUIREMENTS OF:" at 12057.46,1822.64 h60
  text "X" at 11683.96,1686.13 h60
  text "ANSI IPC-A-600F CLASS ->" at 11822.96,1686.13 h60
  text "X" at 13462.02,1686.13 h60
  text "2" at 13580.96,1686.14 h60
  text "1" at 13265.96,1684.64 h60
  text "3" at 13934.96,1684.64 h60
  text "X" at 11686.02,1526.64 h60
  text "UL 94V-0" at 11822.96,1526.64 h60
  text "X" at 12498.02,1526.64 h60
  text "RoHS" at 12634.96,1526.64 h60
  text "OTHER" at 13279.36,1526.64 h60
  text "PER ORDER" at 13676.42,1526.64 h60
  text "ADDITIONAL REQUIREMENTS:" at 11332.46,1385.64 h60
  text "MICROSECTION:" at 11407.23,1270.64 h60
  text "YES" at 12312.96,1270.64 h60
  text "REQUIRED" at 13174.46,1114.49 h60
  text "BARE BOARD ELEC. TEST:" at 11407.23,1111.64 h60
  text "NONE" at 12712.96,1111.64 h60
  text "X" at 13047.46,1111.64 h60
  text "PER ORDER" at 13766.46,1111.64 h60
  text "MANUFACTURER'S UL:" at 11407.23,954.64 h60
  text "RAIL" at 12572.96,950.35 h60
  text "METAL" at 13064.77,950.35 h60
  text "X" at 13440,950 h60
  text "SILK" at 13576.46,950.35 h60
  text ".Layer_Name" at 577,-858.49 h60
M11 Gerber Information:
  lines w10: -292,-930.17 6308,-930.17 ; -292,-726.83 6310,-726.83 ; -292,-523.5 -292,-1133.5 3713,-1133.5 6310,-1133.5 6310,-523.5 -291.5,-523.5 -291.5,-1133.5 1284,-1133.5 ; 2173,-1133.5 2173,-523.5 ; 3440,-726.83 3440,-523.5 ; 4280,-726.83 4280,-523.5 ; 4902,-1140 4902,-937.17
  text "ALL ARTWORK VIEWED FROM TOP SIDE" at -228.5,-655.67 h60
  text "BOARD #:" at 2248,-655.67 h60
  text ".PRJ_Number" at 2793.5,-655.67 h60
  text "REV:" at 3638,-655.67 h60
  text ".PCB_Rev" at 3929.5,-655.67 h60
  text "SVN REV:" at 4476,-655.67 h60
  text ".VersionControl_RevNumber" at 4982,-655.67 h60
  text "LAYER NAME =" at -228.5,-858.49 h60
  text "PLOT NAME =" at -228.5,-1064.34 h60
  text ".plot_File_Name" at 577,-1064.34 h60
  text "GENERATED    :" at 2250,-1064.34 h60
  text ".Print_Date" at 3119.5,-1064.34 h60
  text ".Print_Time" at 3848.5,-1064.34 h60
  text "TEXAS INSTRUMENTS" at 5113,-1064.34 h60
M12 Stackup:
  drawing of 295 lines, arcs and shapes, not listed
  text "Layer" at 2800.58,1305 h60
  text "Name" at 3210.49,1305 h60
  text "Material" at 4140.23,1305 h60
  text "Thickness" at 5000,1305 h60
  text "Constant" at 5649.84,1305 h60
  text "Board Layer Stack" at 6219.7,1305 h60
  text "1" at 2800.58,1185 h60
  text "Top Overlay" at 3210.49,1185 h60
  text "2" at 2800.58,1065 h60
  text "Top Solder" at 3210.49,1065 h60
  text "Solder Resist" at 4140.23,1065 h60
  text "0.40mil" at 5000,1065 h60
  text "3.5" at 5649.84,1065 h60
  text "3" at 2800.58,945 h60
  text "Top Layer" at 3210.49,945 h60
  text "Copper" at 4140.23,945 h60
  text "1.40mil" at 5000,945 h60
  text "4" at 2800.58,825 h60
  text "Dielectric1" at 3210.49,825 h60
  text "FR-4" at 4140.23,825 h60
  text "12.60mil" at 5000,825 h60
  text "4.8" at 5649.84,825 h60
  text "5" at 2800.58,705 h60
  text "GND" at 3210.49,705 h60
  text "Copper" at 4140.23,705 h60
  text "1.40mil" at 5000,705 h60
  text "6" at 2800.58,585 h60
  text "Dielectric2" at 3210.49,585 h60
  text "FR-4" at 4140.23,585 h60
  text "30.00mil" at 5000,585 h60
  text "4.8" at 5649.84,585 h60
  text "7" at 2800.58,465 h60
  text "PWR" at 3210.49,465 h60
  text "Copper" at 4140.23,465 h60
  text "1.40mil" at 5000,465 h60
  text "8" at 2800.58,345 h60
  text "Dielectric3" at 3210.49,345 h60
  text "FR-4" at 4140.23,345 h60
  text "12.60mil" at 5000,345 h60
  text "4.8" at 5649.84,345 h60
  text "9" at 2800.58,225 h60
  text "Bottom Layer" at 3210.49,225 h60
  text "Copper" at 4140.23,225 h60
  text "1.40mil" at 5000,225 h60
  text "10" at 2800.58,105 h60
  text "Bottom Solder" at 3210.49,105 h60
  text "Solder Resist" at 4140.23,105 h60
  text "0.40mil" at 5000,105 h60
  text "3.5" at 5649.84,105 h60
  text "11" at 2800.58,-15 h60
  text "Bottom Overlay" at 3210.49,-15 h60
  text ".Layer_Name" at 577,-858.49 h60
M13 Component Bodies Top:
  text ".Layer_Name" at 577,-858.49 h60
M14 Component Bodies Bottom:
  text ".Layer_Name" at 577,-858.49 h60
M15 Courtyards Top:
  text ".Layer_Name" at 577,-858.49 h60
M16 Courtyards Bottom:
  text ".Layer_Name" at 577,-858.49 h60
Drill Drawing:
  lines w1: 2791.95,1740.77 2802.3,1740.77 2812.65,1730.42 2823,1740.77 2833.35,1740.77 2823,1751.12 2833.35,1761.47 2823,1761.47 2812.65,1771.82 2802.3,1761.47 2791.95,1761.47 2802.3,1751.12 2791.95,1740.77 ; 2791.95,1896.03 2833.35,1896.03 2812.65,1854.63 2791.95,1896.03 ; 2791.95,1978.84 2833.35,1978.84 2833.35,2020.24 2791.95,2020.24 2791.95,1978.84
  lines w12: 2735,1693.16 4761.49,1693.16 ; 2735,2065.79 4761.49,2065.79 ; 3082.63,1568.94 3082.63,2190 ; 3424.38,1568.94 3424.38,2190 ; 4070.4,1568.94 4070.4,2190 ; 4339.33,1568.94 4339.33,2190 ; 2735,1568.94 4761.49,1568.94 4761.49,2190 2735,2190 2735,1568.94
  text "Symbol" at 2809.53,2103.05 h72
  text "Quantity" at 3119.9,2103.05 h72
  text "Finished Hole Size" at 3461.64,2103.05 h72
  text "Plated" at 4107.66,2103.05 h72
  text "Hole Type" at 4376.59,2103.05 h72
  text "5" at 3119.9,1978.84 h60
  text "7.87mil (0.200mm)" at 3461.64,1978.84 h60
  text "PTH" at 4107.66,1978.84 h60
  text "Round" at 4376.59,1978.84 h60
  text "39" at 3119.9,1854.63 h60
  text "10.00mil (0.254mm)" at 3461.64,1854.63 h60
  text "PTH" at 4107.66,1854.63 h60
  text "Round" at 4376.59,1854.63 h60
  text "6" at 3119.9,1730.42 h60
  text "40.00mil (1.016mm)" at 3461.64,1730.42 h60
  text "PTH" at 4107.66,1730.42 h60
  text "Round" at 4376.59,1730.42 h60
  text "50 Total" at 3119.9,1606.21 h60
  text ".Layer_Name" at 577,-858.49 h60

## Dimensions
0,-410.5 to 1000,-410.5 on M2 Board Dimensions
0,0 to 0,355 on M2 Board Dimensions
0,0 to 100,785 on M2 Board Dimensions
